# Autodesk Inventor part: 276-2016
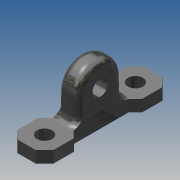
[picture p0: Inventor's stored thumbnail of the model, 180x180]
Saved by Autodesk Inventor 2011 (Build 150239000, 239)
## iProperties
Company: Autodesk Inc.
Created: 2010-06
Part Number: 276-2016
Document SubType Name: Modeling
Designer: Autodesk Inc.
Density: 1 g/cm^3
Catalog Web Link: http://www.vexrobotics.com/276-2016.html
Description: Bearing Blocks mount on a piece of structure and supports a shaft which is offset either above, below, or to the side of the st
Vendor: Innovation First, Inc.
Author: Autodesk Inc.
Title: VEX Robotics Kit of Parts
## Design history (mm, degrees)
sketch "Sketch1"
  geometry: L1 (17.502, 3.327)-(17.502, 6.833); L2 (22.862, 8.255)-(24.767, 10.16); L3 (24.767, 0)-(22.862, 1.905); L4 (24.767, 10.16)-(30.483, 10.16); L5 (30.483, 0)-(24.767, 0); L6 (33.022, 2.538)-(30.483, 0); L7 (33.022, 7.622)-(33.022, 2.538); L8 (30.483, 10.16)-(33.022, 7.622); L9 (13.489, 2.819)-(16.994, 2.819); L10 (16.994, 7.341)-(13.489, 7.341); L11 (12.981, 6.833)-(12.981, 3.327); L12 (22.862, 1.905)-(7.622, 1.905); L13 (7.622, 8.255)-(22.862, 8.255); L14 (7.622, 1.905)-(5.717, 0); L15 (5.717, 10.16)-(7.622, 8.255); L16 (0, 10.16)-(5.717, 10.16); L17 (5.717, 0)-(0, 0); L18 (-2.538, 7.622)-(0, 10.16); L19 (-2.538, 2.538)-(-2.538, 7.622); L20 (0, 0)-(-2.538, 2.538); C1 r 2.311 at (27.942, 5.08); C2 r 2.311 at (2.542, 5.08); 5 further points; 4 other entities
  constraints: 40 end point, 2 centre point, 16 other
extrude "Extrusion1" new body sketch "Sketch1" distance "d0" = 3.175; taper "d1" = -2 deg
workplane "Work Plane1"
sketch "Sketch2"
  geometry: L1 (15.286, 3.177)-(14.954, 3.177); L2 (12.78, 4.402)-(12.704, 6.576); L3 (7.612, 11.481)-(7.628, 11.481); L4 (15.286, 3.177)-(15.24, 0); L5 (2.536, 6.576)-(2.46, 4.402); L6 (0.286, 3.177)-(-0.046, 3.177); L7 (-0.046, 3.177)-(0, 0); L8 (0, 0)-(15.24, 0); L9 (25.335, 0)-(10.003, 0) reference; L10 (17.669, 0)-(17.669, -6.35); L11 (7.62, 6.354)-(7.62, 0); L12 (11.319, -6.35)-(11.319, 0); L13 (24.019, -6.35)-(24.019, 0); A1 r 6.35 centre (17.669, -6.35) between (11.319, -6.35) and (24.019, -6.35); 5 further points; 1 other entity
  constraints: 24 end point, 3 perpendicular, 2 midpoint, 2 point on circle, 2 point on line, 2 tangent, 1 centre point, 1 coincident, 15 other
  dimensions: "d3" = 12.7 diameter of A1
extrude "Extrusion2" join sketch "Sketch2" stored distance "d4" = 3.175; taper "d5" = 0 deg
fillet "Fillet2" dims "d7" = 2.032
fillet "Fillet3" dims "d8" = 2.032
sketch "Sketch3"
  geometry: 4 further points; 1 other entity
  constraints: 1 other
hole "Hole1" sketch "Sketch3" at (7.62, -9.602) diameter "d9" = 4.2418; stored, may be unused: countersink angle "d13" = 82 deg, drill point angle "d15" = 118 deg; dims "d10" = 19.05, "d11" = 9.525, "d12" = 6.35, "d14" = 25.4
sketch "Sketch4"
  geometry: 3 further points
hole "Hole2" sketch "Sketch4" at (-27.942, 5.08), (-2.542, 5.08) diameter "d16" = 4.2418; stored, may be unused: countersink angle "d20" = 82 deg, drill point angle "d22" = 118 deg; dims "d17" = 19.05, "d18" = 9.525, "d19" = 6.35, "d21" = 25.4
extrude "Extrusion3" join sketch "Sketch1" distance "d23" = 0.6858; taper "d24" = -2 deg
body "Solid1"
